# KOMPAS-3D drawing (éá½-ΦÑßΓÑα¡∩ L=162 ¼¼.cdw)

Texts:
  Текст на чертеже
  Размерные надписи
  Шероховатость
  Линия-выноска #1
  Линия-выноска #2
  Линия-выноска #3
  Отклонения формы и база
  Заголовок таблицы
  Ячейка таблицы
  Стрелка вида
  Обозначение изменения
  Фигурная скобка
  Номер узла
  Марка координационной оси
  VRCB
  Выносная надпись
  Обозначение узла
  Марка/позиционное обозначение с линией-выноской
  Марка/позиционное обозначение на линии
  Марка/позиционное обозначение без линии-выноски
  Модуль нормальный
  Число зубьев
  Угол наклона зуба
  Направление линии зуба
  Исходный контур
  Коэффициент смещения
  Степень точности ГОСТ1643-72
  Делительный диаметр
  Symbol
  правое
  ГОСТ 13755-68
  1. HBC 426-495
  2. Допуски на размеры с неуказаными допусками валов - JT14 ,
  отверстий +JT14 , остальные  t /2
  повернуто
  Rz20
  R 0,4MAX
  Лист
  Листов
  Лит.
  Масштаб
  Изм
  №докум.
  Подпись
  Дата
  Разраб.
  Утв.
  Вал-шестерня
  БрГТУ СДМ
  Сталь 40Х ГОСТ 4543-71
Dimensions and other numbers on the sheet: 7; 2 фаски; 23; 2 45; 36; 81; 98; 25; 35; 58; 162; 40; 1,25; 0,011; 0,004; 1; 2,5; 59,45; 0,63; 0,005; 0,007; 2 мм; 27; 13 06 57; 0; 55,45 мм; 0,25; 3; 42; 12; 0,022; 0,086; 5; 1709 ДМ 15 КП 000 00 ЧД; 1:1; 2; 4; 6; 8; 9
